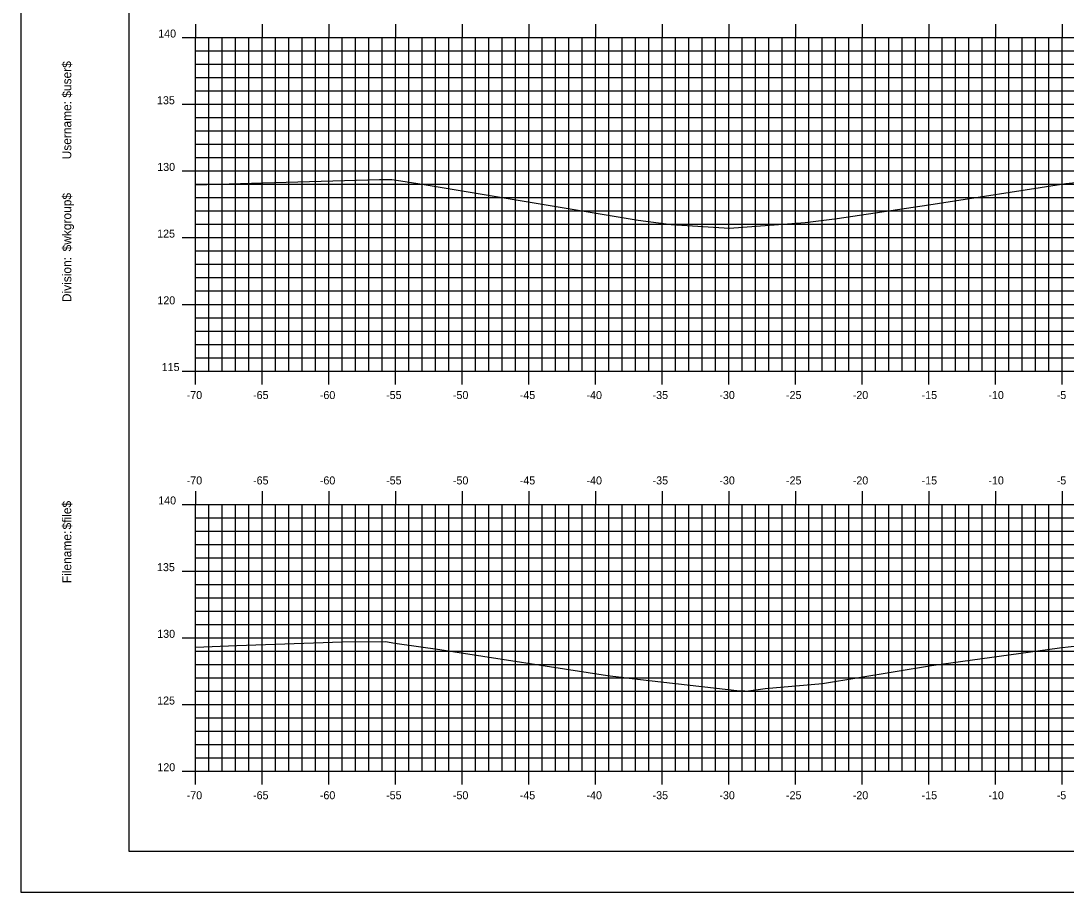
# Model space of a CAD drawing. Extents: x 851073 to 851245, y 365624 to 365734.
# Drawn here: x 851073.2 to 851151.5, y 365624 to 365689.3 of the extents above; entities that cross this region are included whole.
import ezdxf

# ---------------------------------------------------------------- set-up
doc = ezdxf.new("R2010")
doc.units = 0
for name, color, linetype in [('BORDER', 7, 'Continuous'), ('H_V ANNOTATION', 7, 'Continuous'), ('MAJOR', 7, 'Continuous'), ('MINOR', 7, 'Continuous'), ('PLOT BOUNDARY', 7, 'Continuous'), ('S_Roadway_Centerline', 7, 'Continuous')]:
    doc.layers.add(name, color=color, linetype=linetype)

msp = doc.modelspace()

# ---------------------------------------------------------------- linework, layer by layer
at = {"layer": 'BORDER'}
msp.add_lwpolyline([(851081.253, 365627.027), (851241.253, 365627.027), (851241.253, 365732.027), (851081.253, 365732.027)], close=True, dxfattribs=at)
at = {"layer": 'MAJOR'}
for p, q in [((851086.253, 365689.029), (851086.253, 365688.027)), ((851091.253, 365689.029), (851091.253, 365688.027)), ((851096.253, 365689.029), (851096.253, 365688.027)), ((851101.253, 365689.029), (851101.253, 365688.027)), ((851106.253, 365689.029), (851106.253, 365688.027)), ((851111.253, 365689.029), (851111.253, 365688.027)), ((851116.253, 365689.029), (851116.253, 365688.027)), ((851121.253, 365689.029), (851121.253, 365688.027)), ((851126.253, 365689.029), (851126.253, 365688.027)), ((851131.253, 365689.029), (851131.253, 365688.027)), ((851136.253, 365689.029), (851136.253, 365688.027)), ((851141.253, 365689.029), (851141.253, 365688.027)), ((851146.253, 365689.029), (851146.253, 365688.027)), ((851151.253, 365689.029), (851151.253, 365688.027)), ((851085.251, 365688.027), (851086.253, 365688.027)), ((851086.253, 365688.027), (851226.253, 365688.027)), ((851086.253, 365663.027), (851086.253, 365688.027)), ((851086.253, 365663.027), (851086.253, 365688.027)), ((851086.253, 365688.027), (851226.253, 365688.027)), ((851091.253, 365663.027), (851091.253, 365688.027)), ((851096.253, 365663.027), (851096.253, 365688.027)), ((851101.253, 365663.027), (851101.253, 365688.027)), ((851106.253, 365663.027), (851106.253, 365688.027)), ((851111.253, 365663.027), (851111.253, 365688.027)), ((851116.253, 365663.027), (851116.253, 365688.027)), ((851121.253, 365663.027), (851121.253, 365688.027)), ((851126.253, 365663.027), (851126.253, 365688.027)), ((851131.253, 365663.027), (851131.253, 365688.027)), ((851136.253, 365663.027), (851136.253, 365688.027)), ((851141.253, 365663.027), (851141.253, 365688.027)), ((851146.253, 365663.027), (851146.253, 365688.027)), ((851151.253, 365663.027), (851151.253, 365688.027)), ((851085.251, 365683.027), (851086.253, 365683.027)), ((851086.253, 365683.027), (851226.253, 365683.027)), ((851085.251, 365678.027), (851086.253, 365678.027)), ((851086.253, 365678.027), (851226.253, 365678.027)), ((851085.251, 365673.027), (851086.253, 365673.027)), ((851086.253, 365673.027), (851226.253, 365673.027)), ((851085.251, 365668.027), (851086.253, 365668.027)), ((851086.253, 365668.027), (851226.253, 365668.027)), ((851085.251, 365663.027), (851086.253, 365663.027)), ((851086.253, 365663.027), (851226.253, 365663.027)), ((851086.253, 365663.027), (851226.253, 365663.027)), ((851086.253, 365662.025), (851086.253, 365663.027)), ((851091.253, 365662.025), (851091.253, 365663.027)), ((851096.253, 365662.025), (851096.253, 365663.027)), ((851101.253, 365662.025), (851101.253, 365663.027)), ((851106.253, 365662.025), (851106.253, 365663.027)), ((851111.253, 365662.025), (851111.253, 365663.027)), ((851116.253, 365662.025), (851116.253, 365663.027)), ((851121.253, 365662.025), (851121.253, 365663.027)), ((851126.253, 365662.025), (851126.253, 365663.027)), ((851131.253, 365662.025), (851131.253, 365663.027)), ((851136.253, 365662.025), (851136.253, 365663.027)), ((851141.253, 365662.025), (851141.253, 365663.027)), ((851146.253, 365662.025), (851146.253, 365663.027)), ((851151.253, 365662.025), (851151.253, 365663.027)), ((851086.253, 365654.029), (851086.253, 365653.027)), ((851091.253, 365654.029), (851091.253, 365653.027)), ((851096.253, 365654.029), (851096.253, 365653.027)), ((851101.253, 365654.029), (851101.253, 365653.027)), ((851106.253, 365654.029), (851106.253, 365653.027)), ((851111.253, 365654.029), (851111.253, 365653.027)), ((851116.253, 365654.029), (851116.253, 365653.027)), ((851121.253, 365654.029), (851121.253, 365653.027)), ((851126.253, 365654.029), (851126.253, 365653.027)), ((851131.253, 365654.029), (851131.253, 365653.027)), ((851136.253, 365654.029), (851136.253, 365653.027)), ((851141.253, 365654.029), (851141.253, 365653.027)), ((851146.253, 365654.029), (851146.253, 365653.027)), ((851151.253, 365654.029), (851151.253, 365653.027)), ((851085.251, 365653.027), (851086.253, 365653.027)), ((851086.253, 365653.027), (851226.253, 365653.027)), ((851086.253, 365633.027), (851086.253, 365653.027)), ((851086.253, 365633.027), (851086.253, 365653.027)), ((851086.253, 365653.027), (851226.253, 365653.027)), ((851091.253, 365633.027), (851091.253, 365653.027)), ((851096.253, 365633.027), (851096.253, 365653.027)), ((851101.253, 365633.027), (851101.253, 365653.027)), ((851106.253, 365633.027), (851106.253, 365653.027)), ((851111.253, 365633.027), (851111.253, 365653.027)), ((851116.253, 365633.027), (851116.253, 365653.027)), ((851121.253, 365633.027), (851121.253, 365653.027)), ((851126.253, 365633.027), (851126.253, 365653.027)), ((851131.253, 365633.027), (851131.253, 365653.027)), ((851136.253, 365633.027), (851136.253, 365653.027)), ((851141.253, 365633.027), (851141.253, 365653.027)), ((851146.253, 365633.027), (851146.253, 365653.027)), ((851151.253, 365633.027), (851151.253, 365653.027)), ((851085.251, 365648.027), (851086.253, 365648.027)), ((851086.253, 365648.027), (851226.253, 365648.027)), ((851085.251, 365643.027), (851086.253, 365643.027)), ((851086.253, 365643.027), (851226.253, 365643.027)), ((851085.251, 365638.027), (851086.253, 365638.027)), ((851086.253, 365638.027), (851226.253, 365638.027)), ((851085.251, 365633.027), (851086.253, 365633.027)), ((851086.253, 365633.027), (851226.253, 365633.027)), ((851086.253, 365633.027), (851226.253, 365633.027)), ((851086.253, 365632.025), (851086.253, 365633.027)), ((851091.253, 365632.025), (851091.253, 365633.027)), ((851096.253, 365632.025), (851096.253, 365633.027)), ((851101.253, 365632.025), (851101.253, 365633.027)), ((851106.253, 365632.025), (851106.253, 365633.027)), ((851111.253, 365632.025), (851111.253, 365633.027)), ((851116.253, 365632.025), (851116.253, 365633.027)), ((851121.253, 365632.025), (851121.253, 365633.027)), ((851126.253, 365632.025), (851126.253, 365633.027)), ((851131.253, 365632.025), (851131.253, 365633.027)), ((851136.253, 365632.025), (851136.253, 365633.027)), ((851141.253, 365632.025), (851141.253, 365633.027)), ((851146.253, 365632.025), (851146.253, 365633.027)), ((851151.253, 365632.025), (851151.253, 365633.027))]:
    msp.add_line(p, q, dxfattribs=at)
at = {"layer": 'MINOR'}
for p, q in [((851087.253, 365663.027), (851087.253, 365688.027)), ((851088.253, 365663.027), (851088.253, 365688.027)), ((851089.253, 365663.027), (851089.253, 365688.027)), ((851090.253, 365663.027), (851090.253, 365688.027)), ((851092.253, 365663.027), (851092.253, 365688.027)), ((851093.253, 365663.027), (851093.253, 365688.027)), ((851094.253, 365663.027), (851094.253, 365688.027)), ((851095.253, 365663.027), (851095.253, 365688.027)), ((851097.253, 365663.027), (851097.253, 365688.027)), ((851098.253, 365663.027), (851098.253, 365688.027)), ((851099.253, 365663.027), (851099.253, 365688.027)), ((851100.253, 365663.027), (851100.253, 365688.027)), ((851102.253, 365663.027), (851102.253, 365688.027)), ((851103.253, 365663.027), (851103.253, 365688.027)), ((851104.253, 365663.027), (851104.253, 365688.027)), ((851105.253, 365663.027), (851105.253, 365688.027)), ((851107.253, 365663.027), (851107.253, 365688.027)), ((851108.253, 365663.027), (851108.253, 365688.027)), ((851109.253, 365663.027), (851109.253, 365688.027)), ((851110.253, 365663.027), (851110.253, 365688.027)), ((851112.253, 365663.027), (851112.253, 365688.027)), ((851113.253, 365663.027), (851113.253, 365688.027)), ((851114.253, 365663.027), (851114.253, 365688.027)), ((851115.253, 365663.027), (851115.253, 365688.027)), ((851117.253, 365663.027), (851117.253, 365688.027)), ((851118.253, 365663.027), (851118.253, 365688.027)), ((851119.253, 365663.027), (851119.253, 365688.027)), ((851120.253, 365663.027), (851120.253, 365688.027)), ((851122.253, 365663.027), (851122.253, 365688.027)), ((851123.253, 365663.027), (851123.253, 365688.027)), ((851124.253, 365663.027), (851124.253, 365688.027)), ((851125.253, 365663.027), (851125.253, 365688.027)), ((851127.253, 365663.027), (851127.253, 365688.027)), ((851128.253, 365663.027), (851128.253, 365688.027)), ((851129.253, 365663.027), (851129.253, 365688.027)), ((851130.253, 365663.027), (851130.253, 365688.027)), ((851132.253, 365663.027), (851132.253, 365688.027)), ((851133.253, 365663.027), (851133.253, 365688.027)), ((851134.253, 365663.027), (851134.253, 365688.027)), ((851135.253, 365663.027), (851135.253, 365688.027)), ((851137.253, 365663.027), (851137.253, 365688.027)), ((851138.253, 365663.027), (851138.253, 365688.027)), ((851139.253, 365663.027), (851139.253, 365688.027)), ((851140.253, 365663.027), (851140.253, 365688.027)), ((851142.253, 365663.027), (851142.253, 365688.027)), ((851143.253, 365663.027), (851143.253, 365688.027)), ((851144.253, 365663.027), (851144.253, 365688.027)), ((851145.253, 365663.027), (851145.253, 365688.027)), ((851147.253, 365663.027), (851147.253, 365688.027)), ((851148.253, 365663.027), (851148.253, 365688.027)), ((851149.253, 365663.027), (851149.253, 365688.027)), ((851150.253, 365663.027), (851150.253, 365688.027)), ((851086.253, 365687.027), (851226.253, 365687.027)), ((851086.253, 365687.027), (851087.255, 365687.027)), ((851086.253, 365686.027), (851226.253, 365686.027)), ((851086.253, 365686.027), (851087.255, 365686.027)), ((851086.253, 365685.027), (851226.253, 365685.027)), ((851086.253, 365685.027), (851087.255, 365685.027)), ((851086.253, 365684.027), (851226.253, 365684.027)), ((851086.253, 365684.027), (851087.255, 365684.027)), ((851086.253, 365682.027), (851226.253, 365682.027)), ((851086.253, 365682.027), (851087.255, 365682.027)), ((851086.253, 365681.027), (851226.253, 365681.027)), ((851086.253, 365681.027), (851087.255, 365681.027)), ((851086.253, 365680.027), (851226.253, 365680.027)), ((851086.253, 365680.027), (851087.255, 365680.027)), ((851086.253, 365679.027), (851226.253, 365679.027)), ((851086.253, 365679.027), (851087.255, 365679.027)), ((851086.253, 365677.027), (851226.253, 365677.027)), ((851086.253, 365677.027), (851087.255, 365677.027)), ((851086.253, 365676.027), (851226.253, 365676.027)), ((851086.253, 365676.027), (851087.255, 365676.027)), ((851086.253, 365675.027), (851226.253, 365675.027)), ((851086.253, 365675.027), (851087.255, 365675.027)), ((851086.253, 365674.027), (851226.253, 365674.027)), ((851086.253, 365674.027), (851087.255, 365674.027)), ((851086.253, 365672.027), (851226.253, 365672.027)), ((851086.253, 365672.027), (851087.255, 365672.027)), ((851086.253, 365671.027), (851226.253, 365671.027)), ((851086.253, 365671.027), (851087.255, 365671.027)), ((851086.253, 365670.027), (851226.253, 365670.027)), ((851086.253, 365670.027), (851087.255, 365670.027)), ((851086.253, 365669.027), (851226.253, 365669.027)), ((851086.253, 365669.027), (851087.255, 365669.027)), ((851086.253, 365667.027), (851226.253, 365667.027)), ((851086.253, 365667.027), (851087.255, 365667.027)), ((851086.253, 365666.027), (851226.253, 365666.027)), ((851086.253, 365666.027), (851087.255, 365666.027)), ((851086.253, 365665.027), (851226.253, 365665.027)), ((851086.253, 365665.027), (851087.255, 365665.027)), ((851086.253, 365664.027), (851226.253, 365664.027)), ((851086.253, 365664.027), (851087.255, 365664.027)), ((851087.253, 365633.027), (851087.253, 365653.027)), ((851088.253, 365633.027), (851088.253, 365653.027)), ((851089.253, 365633.027), (851089.253, 365653.027)), ((851090.253, 365633.027), (851090.253, 365653.027)), ((851092.253, 365633.027), (851092.253, 365653.027)), ((851093.253, 365633.027), (851093.253, 365653.027)), ((851094.253, 365633.027), (851094.253, 365653.027)), ((851095.253, 365633.027), (851095.253, 365653.027)), ((851097.253, 365633.027), (851097.253, 365653.027)), ((851098.253, 365633.027), (851098.253, 365653.027)), ((851099.253, 365633.027), (851099.253, 365653.027)), ((851100.253, 365633.027), (851100.253, 365653.027)), ((851102.253, 365633.027), (851102.253, 365653.027)), ((851103.253, 365633.027), (851103.253, 365653.027)), ((851104.253, 365633.027), (851104.253, 365653.027)), ((851105.253, 365633.027), (851105.253, 365653.027)), ((851107.253, 365633.027), (851107.253, 365653.027)), ((851108.253, 365633.027), (851108.253, 365653.027)), ((851109.253, 365633.027), (851109.253, 365653.027)), ((851110.253, 365633.027), (851110.253, 365653.027)), ((851112.253, 365633.027), (851112.253, 365653.027)), ((851113.253, 365633.027), (851113.253, 365653.027)), ((851114.253, 365633.027), (851114.253, 365653.027)), ((851115.253, 365633.027), (851115.253, 365653.027)), ((851117.253, 365633.027), (851117.253, 365653.027)), ((851118.253, 365633.027), (851118.253, 365653.027)), ((851119.253, 365633.027), (851119.253, 365653.027)), ((851120.253, 365633.027), (851120.253, 365653.027)), ((851122.253, 365633.027), (851122.253, 365653.027)), ((851123.253, 365633.027), (851123.253, 365653.027)), ((851124.253, 365633.027), (851124.253, 365653.027)), ((851125.253, 365633.027), (851125.253, 365653.027)), ((851127.253, 365633.027), (851127.253, 365653.027)), ((851128.253, 365633.027), (851128.253, 365653.027)), ((851129.253, 365633.027), (851129.253, 365653.027)), ((851130.253, 365633.027), (851130.253, 365653.027)), ((851132.253, 365633.027), (851132.253, 365653.027)), ((851133.253, 365633.027), (851133.253, 365653.027)), ((851134.253, 365633.027), (851134.253, 365653.027)), ((851135.253, 365633.027), (851135.253, 365653.027)), ((851137.253, 365633.027), (851137.253, 365653.027)), ((851138.253, 365633.027), (851138.253, 365653.027)), ((851139.253, 365633.027), (851139.253, 365653.027)), ((851140.253, 365633.027), (851140.253, 365653.027)), ((851142.253, 365633.027), (851142.253, 365653.027)), ((851143.253, 365633.027), (851143.253, 365653.027)), ((851144.253, 365633.027), (851144.253, 365653.027)), ((851145.253, 365633.027), (851145.253, 365653.027)), ((851147.253, 365633.027), (851147.253, 365653.027)), ((851148.253, 365633.027), (851148.253, 365653.027)), ((851149.253, 365633.027), (851149.253, 365653.027)), ((851150.253, 365633.027), (851150.253, 365653.027)), ((851086.253, 365652.027), (851226.253, 365652.027)), ((851086.253, 365652.027), (851087.255, 365652.027)), ((851086.253, 365651.027), (851226.253, 365651.027)), ((851086.253, 365651.027), (851087.255, 365651.027)), ((851086.253, 365650.027), (851226.253, 365650.027)), ((851086.253, 365650.027), (851087.255, 365650.027)), ((851086.253, 365649.027), (851226.253, 365649.027)), ((851086.253, 365649.027), (851087.255, 365649.027)), ((851086.253, 365647.027), (851226.253, 365647.027)), ((851086.253, 365647.027), (851087.255, 365647.027)), ((851086.253, 365646.027), (851226.253, 365646.027)), ((851086.253, 365646.027), (851087.255, 365646.027)), ((851086.253, 365645.027), (851226.253, 365645.027)), ((851086.253, 365645.027), (851087.255, 365645.027)), ((851086.253, 365644.027), (851226.253, 365644.027)), ((851086.253, 365644.027), (851087.255, 365644.027)), ((851086.253, 365642.027), (851226.253, 365642.027)), ((851086.253, 365642.027), (851087.255, 365642.027)), ((851086.253, 365641.027), (851226.253, 365641.027)), ((851086.253, 365641.027), (851087.255, 365641.027)), ((851086.253, 365640.027), (851226.253, 365640.027)), ((851086.253, 365640.027), (851087.255, 365640.027)), ((851086.253, 365639.027), (851226.253, 365639.027)), ((851086.253, 365639.027), (851087.255, 365639.027)), ((851086.253, 365637.027), (851226.253, 365637.027)), ((851086.253, 365637.027), (851087.255, 365637.027)), ((851086.253, 365636.027), (851226.253, 365636.027)), ((851086.253, 365636.027), (851087.255, 365636.027)), ((851086.253, 365635.027), (851226.253, 365635.027)), ((851086.253, 365635.027), (851087.255, 365635.027)), ((851086.253, 365634.027), (851226.253, 365634.027)), ((851086.253, 365634.027), (851087.255, 365634.027))]:
    msp.add_line(p, q, dxfattribs=at)
at = {"layer": 'PLOT BOUNDARY'}
msp.add_lwpolyline([(851073.159, 365623.968), (851243.159, 365623.968), (851243.159, 365733.968), (851073.159, 365733.968)], close=True, dxfattribs=at)
at = {"layer": 'S_Roadway_Centerline'}
for points in [[(851086.253, 365676.983), (851091.296, 365677.123), (851100.063, 365677.381), (851100.966, 365677.38), (851101.66, 365677.277), (851103.394, 365677.004), (851119.453, 365674.342), (851121.914, 365674.012), (851126.3, 365673.728), (851131.973, 365674.163), (851134.383, 365674.467), (851141.252, 365675.485), (851151.531, 365677.075), (851152.804, 365677.205)], [(851086.253, 365642.317), (851089.354, 365642.457), (851097.246, 365642.731), (851100.503, 365642.752), (851101.195, 365642.623), (851104.576, 365642.142), (851117.151, 365640.195), (851119.393, 365639.939), (851127.081, 365639.052), (851127.461, 365639.052), (851127.554, 365639.037), (851128.97, 365639.22), (851133.273, 365639.614), (851141.459, 365640.961), (851151.044, 365642.279), (851152.802, 365642.489)]]:
    msp.add_lwpolyline(points, dxfattribs=at)

# ---------------------------------------------------------------- texts
at = {"layer": 'BORDER'}
for s, p in [('$user$', (851076.938, 365683.518)), ('Username:', (851076.938, 365678.895)), ('$wkgroup$', (851076.938, 365671.996)), ('Division:', (851076.938, 365668.193)), ('$file$', (851076.938, 365651.152)), ('Filename:', (851076.938, 365647.125))]:
    msp.add_text(s, height=0.6696, rotation=90, dxfattribs=at).set_placement(p)
at = {"layer": 'H_V ANNOTATION'}
for s, p in [('140', (851083.457, 365688.027)), ('135', (851083.366, 365683.027)), ('130', (851083.382, 365678.027)), ('125', (851083.377, 365673.027)), ('120', (851083.393, 365668.027)), ('115', (851083.72, 365663.027)), ('-70', (851085.594, 365660.927)), ('-65', (851090.57, 365660.927)), ('-60', (851095.578, 365660.927)), ('-55', (851100.549, 365660.927)), ('-50', (851105.557, 365660.927)), ('-45', (851110.57, 365660.927)), ('-40', (851115.578, 365660.927)), ('-35', (851120.533, 365660.927)), ('-30', (851125.541, 365660.927)), ('-25', (851130.538, 365660.927)), ('-20', (851135.546, 365660.927)), ('-15', (851140.709, 365660.927)), ('-10', (851145.717, 365660.927)), ('-5', (851150.843, 365660.927)), ('-70', (851085.594, 365654.527)), ('-65', (851090.57, 365654.527)), ('-60', (851095.578, 365654.527)), ('-55', (851100.549, 365654.527)), ('-50', (851105.557, 365654.527)), ('-45', (851110.57, 365654.527)), ('-40', (851115.578, 365654.527)), ('-35', (851120.533, 365654.527)), ('-30', (851125.541, 365654.527)), ('-25', (851130.538, 365654.527)), ('-20', (851135.546, 365654.527)), ('-15', (851140.709, 365654.527)), ('-10', (851145.717, 365654.527)), ('-5', (851150.843, 365654.527)), ('140', (851083.457, 365653.027)), ('135', (851083.366, 365648.027)), ('130', (851083.382, 365643.027)), ('125', (851083.377, 365638.027)), ('120', (851083.393, 365633.027)), ('-70', (851085.594, 365630.927)), ('-65', (851090.57, 365630.927)), ('-60', (851095.578, 365630.927)), ('-55', (851100.549, 365630.927)), ('-50', (851105.557, 365630.927)), ('-45', (851110.57, 365630.927)), ('-40', (851115.578, 365630.927)), ('-35', (851120.533, 365630.927)), ('-30', (851125.541, 365630.927)), ('-25', (851130.538, 365630.927)), ('-20', (851135.546, 365630.927)), ('-15', (851140.709, 365630.927)), ('-10', (851145.717, 365630.927)), ('-5', (851150.843, 365630.927))]:
    msp.add_text(s, height=0.6, dxfattribs=at).set_placement(p)
at = {"layer": 'MAJOR'}
for p in [(851086.248, 365663.027), (851086.248, 365633.027)]:
    msp.add_text('-', height=0.006, dxfattribs=at).set_placement(p)

doc.saveas('drawing.dxf')
